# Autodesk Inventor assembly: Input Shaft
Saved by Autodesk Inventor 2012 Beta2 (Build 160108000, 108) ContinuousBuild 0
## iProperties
Created: 2011-01
Part Number: Input Shaft
Document SubType Name: Assembly
Designer: Beta-8540w
ClientObjectVersion: 1
Author: Beta-8540w
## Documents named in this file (2)
- C:\Inventor 2012 Essentials\Assemblies\Chapter 8\Design Accelerators\Shaft c8-04.iam
- C:\Inventor 2012 Essentials\Assemblies\Chapter 8\Design Accelerators\Shaft c8-04.ipt
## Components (1 placed, 1 different names)
1. Input Shaft:1
